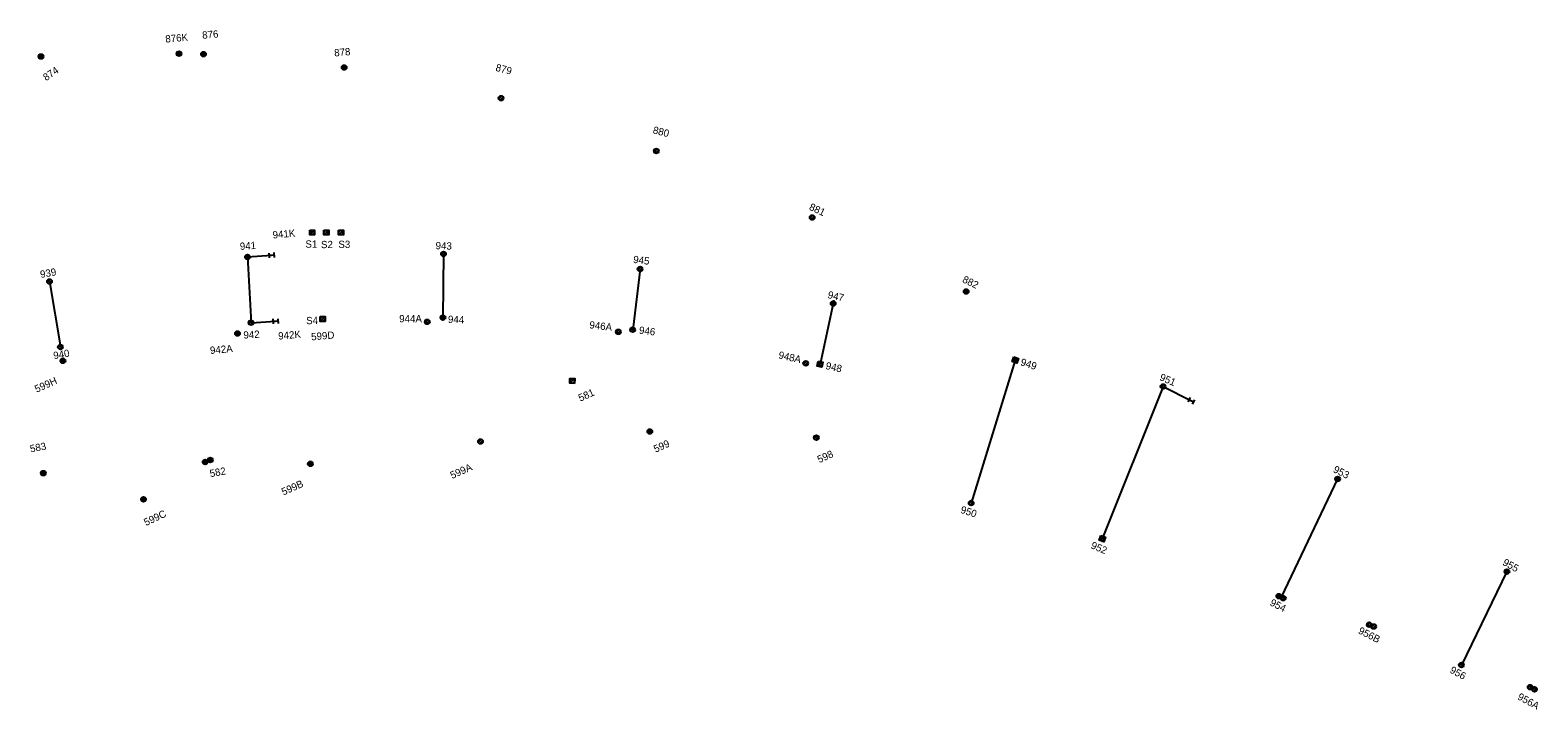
# Model space of a CAD drawing. Extents: x -595867 to -593796, y -1159595 to -1157495.
# Drawn here: x -594401.8 to -594091.2, y -1157744.8 to -1157604.8 of the extents above; entities that cross this region are included whole.
import ezdxf

# ---------------------------------------------------------------- set-up
doc = ezdxf.new("R2010")
doc.units = 0
doc.layers.add('BVK_kanalizace_jednotna_nova', color=7, linetype='Continuous')
doc.layers.add('Teplarny Horkovod', color=7, linetype='Continuous')

# ---------------------------------------------------------------- blocks, each defined once
blk = doc.blocks.new('C725')
at = {"layer": 'Teplarny Horkovod'}
for p, q in [((-0.46, -0.18), (0.18, 0.46)), ((-0.2, -0.45), (0.45, 0.2))]:
    blk.add_line(p, q, dxfattribs=at)
blk.add_circle((0, 0), 0.5, dxfattribs=at)
blk = doc.blocks.new('C662')
at = {"layer": 'Teplarny Horkovod'}
for p, q in [((-0.5, 0.5), (0.5, 0.5)), ((0, 0.5), (0, -0.5)), ((-0.5, -0.5), (0.5, -0.5))]:
    blk.add_line(p, q, dxfattribs=at)
blk = doc.blocks.new('C661_3')
at = {"layer": 'Teplarny Horkovod'}
for p, q in [((-0.5, 0.03), (-0.03, 0.5)), ((-0.5, -0.5), (0.5, 0.5)), ((0.03, -0.5), (0.5, -0.03))]:
    blk.add_line(p, q, dxfattribs=at)
blk.add_lwpolyline([(-0.5, 0.5), (0.5, 0.5), (0.5, -0.5), (-0.5, -0.5)], close=True, dxfattribs=at)
blk.add_lwpolyline([(-0.5, 0.5), (0.5, 0.5), (0.5, -0.5), (-0.5, -0.5), (-0.5, 0.5)], dxfattribs=at)
blk = doc.blocks.new('C725_1')
at = {"layer": 'Teplarny Horkovod'}
for p, q in [((-0.46, -0.18), (0.19, 0.46)), ((-0.2, -0.45), (0.45, 0.2))]:
    blk.add_line(p, q, dxfattribs=at)
blk.add_circle((0, 0), 0.5, dxfattribs=at)

msp = doc.modelspace()

# ---------------------------------------------------------------- linework, layer by layer
at = {"layer": 'BVK_kanalizace_jednotna_nova'}
for p, q in [((-594399.88, -1157610.6), (-594399.51, -1157609.76)), ((-594399.55, -1157610.76), (-594399.17, -1157609.91)), ((-594371.44, -1157610.01), (-594371.07, -1157609.17)), ((-594371.1, -1157610.17), (-594370.73, -1157609.32)), ((-594366.41, -1157610.12), (-594366.04, -1157609.28)), ((-594366.08, -1157610.28), (-594365.7, -1157609.43)), ((-594337.42, -1157612.86), (-594337.05, -1157612.02)), ((-594337.08, -1157613.02), (-594336.71, -1157612.17)), ((-594305.2, -1157619.01), (-594304.56, -1157618.37)), ((-594304.94, -1157619.28), (-594304.29, -1157618.63)), ((-594273.22, -1157629.91), (-594272.58, -1157629.27)), ((-594272.96, -1157630.18), (-594272.31, -1157629.53)), ((-594359.41, -1157667.67), (-594359.04, -1157666.83)), ((-594359.08, -1157667.83), (-594358.7, -1157666.98)), ((-594395.31, -1157673.32), (-594395.06, -1157672.45)), ((-594394.96, -1157673.44), (-594394.7, -1157672.54)), ((-594289.55, -1157676.62), (-594290.58, -1157677.58)), ((-594290.08, -1157676.6), (-594290.57, -1157677.06)), ((-594289.57, -1157677.15), (-594290.05, -1157677.6)), ((-594274.56, -1157687.68), (-594273.92, -1157687.04)), ((-594274.3, -1157687.95), (-594273.65, -1157687.3)), ((-594240.25, -1157688.94), (-594239.6, -1157688.3)), ((-594239.99, -1157689.21), (-594239.34, -1157688.56)), ((-594309.44, -1157689.75), (-594308.8, -1157689.11)), ((-594309.18, -1157690.02), (-594308.53, -1157689.37)), ((-594365.82, -1157694.28), (-594365.98, -1157693.38)), ((-594365.45, -1157694.23), (-594365.61, -1157693.31)), ((-594364.75, -1157693.85), (-594364.91, -1157692.95)), ((-594364.38, -1157693.79), (-594364.55, -1157692.88)), ((-594344.38, -1157694.51), (-594344.01, -1157693.67)), ((-594344.05, -1157694.67), (-594343.67, -1157693.82)), ((-594399.15, -1157696.57), (-594399.31, -1157695.67)), ((-594398.78, -1157696.51), (-594398.94, -1157695.6)), ((-594378.76, -1157701.82), (-594378.39, -1157700.98)), ((-594378.43, -1157701.98), (-594378.05, -1157701.13)), ((-594145.02, -1157721.4), (-594144.19, -1157721.07)), ((-594144.9, -1157721.76), (-594144.02, -1157721.41)), ((-594144.1, -1157721.8), (-594143.27, -1157721.47)), ((-594143.98, -1157722.16), (-594143.1, -1157721.81))]:
    msp.add_line(p, q, dxfattribs=at)
msp.add_lwpolyline([(-594289.59, -1157677.61), (-594290.59, -1157677.58), (-594290.55, -1157676.58), (-594289.55, -1157676.62)], close=True, dxfattribs=at)
msp.add_lwpolyline([(-594289.59, -1157677.61), (-594290.59, -1157677.58), (-594290.55, -1157676.58), (-594289.55, -1157676.62), (-594289.59, -1157677.61)], dxfattribs=at)
for centre in [(-594399.52, -1157610.26), (-594399.52, -1157610.26), (-594371.08, -1157609.67), (-594371.08, -1157609.67), (-594366.05, -1157609.78), (-594366.05, -1157609.78), (-594337.06, -1157612.52), (-594337.06, -1157612.52), (-594304.74, -1157618.83), (-594304.74, -1157618.83), (-594272.76, -1157629.73), (-594272.76, -1157629.73), (-594359.05, -1157667.33), (-594359.05, -1157667.33), (-594395, -1157672.94), (-594395, -1157672.94), (-594274.1, -1157687.5), (-594274.1, -1157687.5), (-594239.79, -1157688.76), (-594239.79, -1157688.76), (-594308.98, -1157689.57), (-594308.98, -1157689.57), (-594365.71, -1157693.8), (-594365.71, -1157693.8), (-594364.64, -1157693.37), (-594364.64, -1157693.37), (-594344.02, -1157694.17), (-594344.02, -1157694.17), (-594399.04, -1157696.09), (-594399.04, -1157696.09), (-594378.4, -1157701.48), (-594378.4, -1157701.48), (-594144.52, -1157721.44), (-594144.52, -1157721.44), (-594143.6, -1157721.84), (-594143.6, -1157721.84)]:
    msp.add_circle(centre, 0.5, dxfattribs=at)
at = {"layer": 'Teplarny Horkovod'}
for p, q in [((-594356.99, -1157651.56), (-594352.04, -1157651.2)), ((-594316.6, -1157650.93), (-594316.72, -1157664.04)), ((-594356.99, -1157651.56), (-594356.25, -1157665.09)), ((-594276.1, -1157654.03), (-594277.62, -1157666.55)), ((-594397.76, -1157656.62), (-594395.52, -1157670.09)), ((-594236.31, -1157661.16), (-594239.02, -1157673.63)), ((-594236.15, -1157660.72), (-594236.13, -1157660.69)), ((-594356.25, -1157665.09), (-594351.2, -1157664.8)), ((-594198.81, -1157672.79), (-594207.9, -1157702.25)), ((-594168.36, -1157678.25), (-594180.88, -1157709.59)), ((-594168.36, -1157678.25), (-594162.49, -1157681.2)), ((-594132.4, -1157697.28), (-594144.04, -1157721.6)), ((-594097.52, -1157716.37), (-594106.9, -1157735.61))]:
    msp.add_line(p, q, dxfattribs=at)
msp.add_lwpolyline([(-594236.4, -1157660.66), (-594236.04, -1157660.74)], dxfattribs=at)
msp.add_arc((-594236.31, -1157661.16), 0.5, 56.2737, 100.3796, dxfattribs=at)

# ---------------------------------------------------------------- block references
for name, p in [('C725', (-594240.66, -1157643.42)), ('C661_3', (-594343.64, -1157646.52)), ('C661_3', (-594340.75, -1157646.51)), ('C661_3', (-594337.73, -1157646.5)), ('C725', (-594356.99, -1157651.56)), ('C725', (-594316.6, -1157650.93)), ('C725', (-594276.1, -1157654.03)), ('C725', (-594397.76, -1157656.62)), ('C725', (-594208.93, -1157658.66)), ('C725', (-594316.72, -1157664.04)), ('C725', (-594236.31, -1157661.16)), ('C725', (-594356.25, -1157665.09)), ('C661_3', (-594341.5, -1157664.33)), ('C725', (-594319.94, -1157664.93)), ('C725', (-594280.58, -1157666.97)), ('C725', (-594277.62, -1157666.55)), ('C725', (-594395.52, -1157670.09)), ('C725', (-594241.97, -1157673.47)), ('C725', (-594168.36, -1157678.25)), ('C725_1', (-594365.71, -1157693.8)), ('C725_1', (-594364.64, -1157693.37)), ('C725_1', (-594399.04, -1157696.09)), ('C725', (-594132.4, -1157697.28)), ('C725', (-594207.9, -1157702.25)), ('C725', (-594097.52, -1157716.37)), ('C725', (-594125.88, -1157727.31)), ('C725', (-594124.97, -1157727.68)), ('C725', (-594106.9, -1157735.61)), ('C725', (-594092.74, -1157740.17)), ('C725', (-594091.84, -1157740.61))]:
    msp.add_blockref(name, p, dxfattribs=at)
for name, p, xscale, yscale, rotation in [('C662', (-594352.04, -1157651.2), 0.9999991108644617, 0.9999991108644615, -85.61746041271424), ('C662', (-594351.2, -1157664.8), 1.0000027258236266, 1.000002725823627, -87.11970121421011), ('C661_3', (-594198.81, -1157672.79), 1.0000004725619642, 1.000000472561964, -18.57272686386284), ('C661_3', (-594239.02, -1157673.63), 0.9999991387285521, 0.999999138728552, -11.739470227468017), ('C662', (-594162.49, -1157681.2), 1.0000014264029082, 1.0000014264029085, 62.66400800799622), ('C661_3', (-594180.88, -1157709.59), 1.0000044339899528, 1.0000044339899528, -20.07829687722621)]:
    msp.add_blockref(name, p, dxfattribs=dict(at, xscale=xscale, yscale=yscale, rotation=rotation))

# ---------------------------------------------------------------- texts
at = {"layer": 'BVK_kanalizace_jednotna_nova'}
for s, rotation, p in [('876K', 4.97, (-594373.84, -1157607.41)), ('876', 4.97, (-594366.25, -1157606.62)), ('878', 4.97, (-594339.06, -1157610.26)), ('874', 34.56, (-594398.46, -1157615.36)), ('879', 345.6326, (-594305.98, -1157613.19)), ('880', 345.6326, (-594273.58, -1157626.07)), ('941K', 4.97, (-594351.74, -1157647.77)), ('942K', 4.97, (-594350.58, -1157668.59)), ('942A', 4.97, (-594364.64, -1157671.54)), ('599D', 4.97, (-594343.8, -1157668.75)), ('599H', 24.1252, (-594400.42, -1157679.54)), ('581', 24.1252, (-594288.41, -1157681.37)), ('583', 10.5999, (-594401.64, -1157691.83)), ('599', 24.1252, (-594272.9, -1157691.89)), ('598', 24.1252, (-594239.18, -1157694.04)), ('599A', 24.1252, (-594314.81, -1157697.31)), ('582', 10.5999, (-594364.62, -1157696.93)), ('599B', 24.1252, (-594349.57, -1157700.71)), ('599C', 25.28, (-594377.89, -1157707))]:
    msp.add_text(s, height=1.5, rotation=rotation, dxfattribs=at).set_placement(p)
for s, p in [('S1', (-594345.05, -1157649.65)), ('S3', (-594338.26, -1157649.7)), ('S2', (-594341.84, -1157649.74))]:
    msp.add_text(s, height=1.5, dxfattribs=at).set_placement(p)
at = {"layer": 'Teplarny Horkovod'}
for s, rotation, p in [('881', 334.8684, (-594241.42, -1157641.76)), ('941', 3.6583, (-594358.51, -1157650.11)), ('943', 358.2533, (-594318.25, -1157649.95)), ('945', 352.868, (-594277.59, -1157652.76)), ('939', 10.1177, (-594399.56, -1157655.9)), ('882', 334.1797, (-594209.85, -1157656.69)), ('947', 347.4146, (-594237.55, -1157660.01)), ('944A', 359.9625, (-594325.73, -1157665.01)), ('944', 358.2533, (-594315.7, -1157665.13)), ('942', 3.6583, (-594357.77, -1157668.39)), ('S4', 1.5044, (-594344.88, -1157665.42)), ('946A', 353.4234, (-594286.61, -1157666.24)), ('946', 352.868, (-594276.39, -1157667.33)), ('940', 10.1177, (-594396.84, -1157672.64)), ('948A', 347.4146, (-594247.7, -1157672.42)), ('949', 342.1339, (-594197.86, -1157673.82)), ('948', 347.4146, (-594237.98, -1157674.63)), ('951', 336.9971, (-594169.22, -1157676.88)), ('953', 333.1963, (-594133.46, -1157695.8)), ('950', 342.1339, (-594210.22, -1157704.23)), ('952', 336.9971, (-594183.38, -1157711.5)), ('955', 331.2284, (-594098.55, -1157714.92)), ('954', 333.1963, (-594146.49, -1157723.24)), ('956B', 333.1963, (-594128.29, -1157729.02)), ('956', 331.2284, (-594109.42, -1157737.09)), ('956A', 331.2284, (-594095.49, -1157742.59))]:
    msp.add_text(s, height=1.5, rotation=rotation, dxfattribs=at).set_placement(p)

doc.saveas('drawing.dxf')
